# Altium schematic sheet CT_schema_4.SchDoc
size 529 x 503 mm
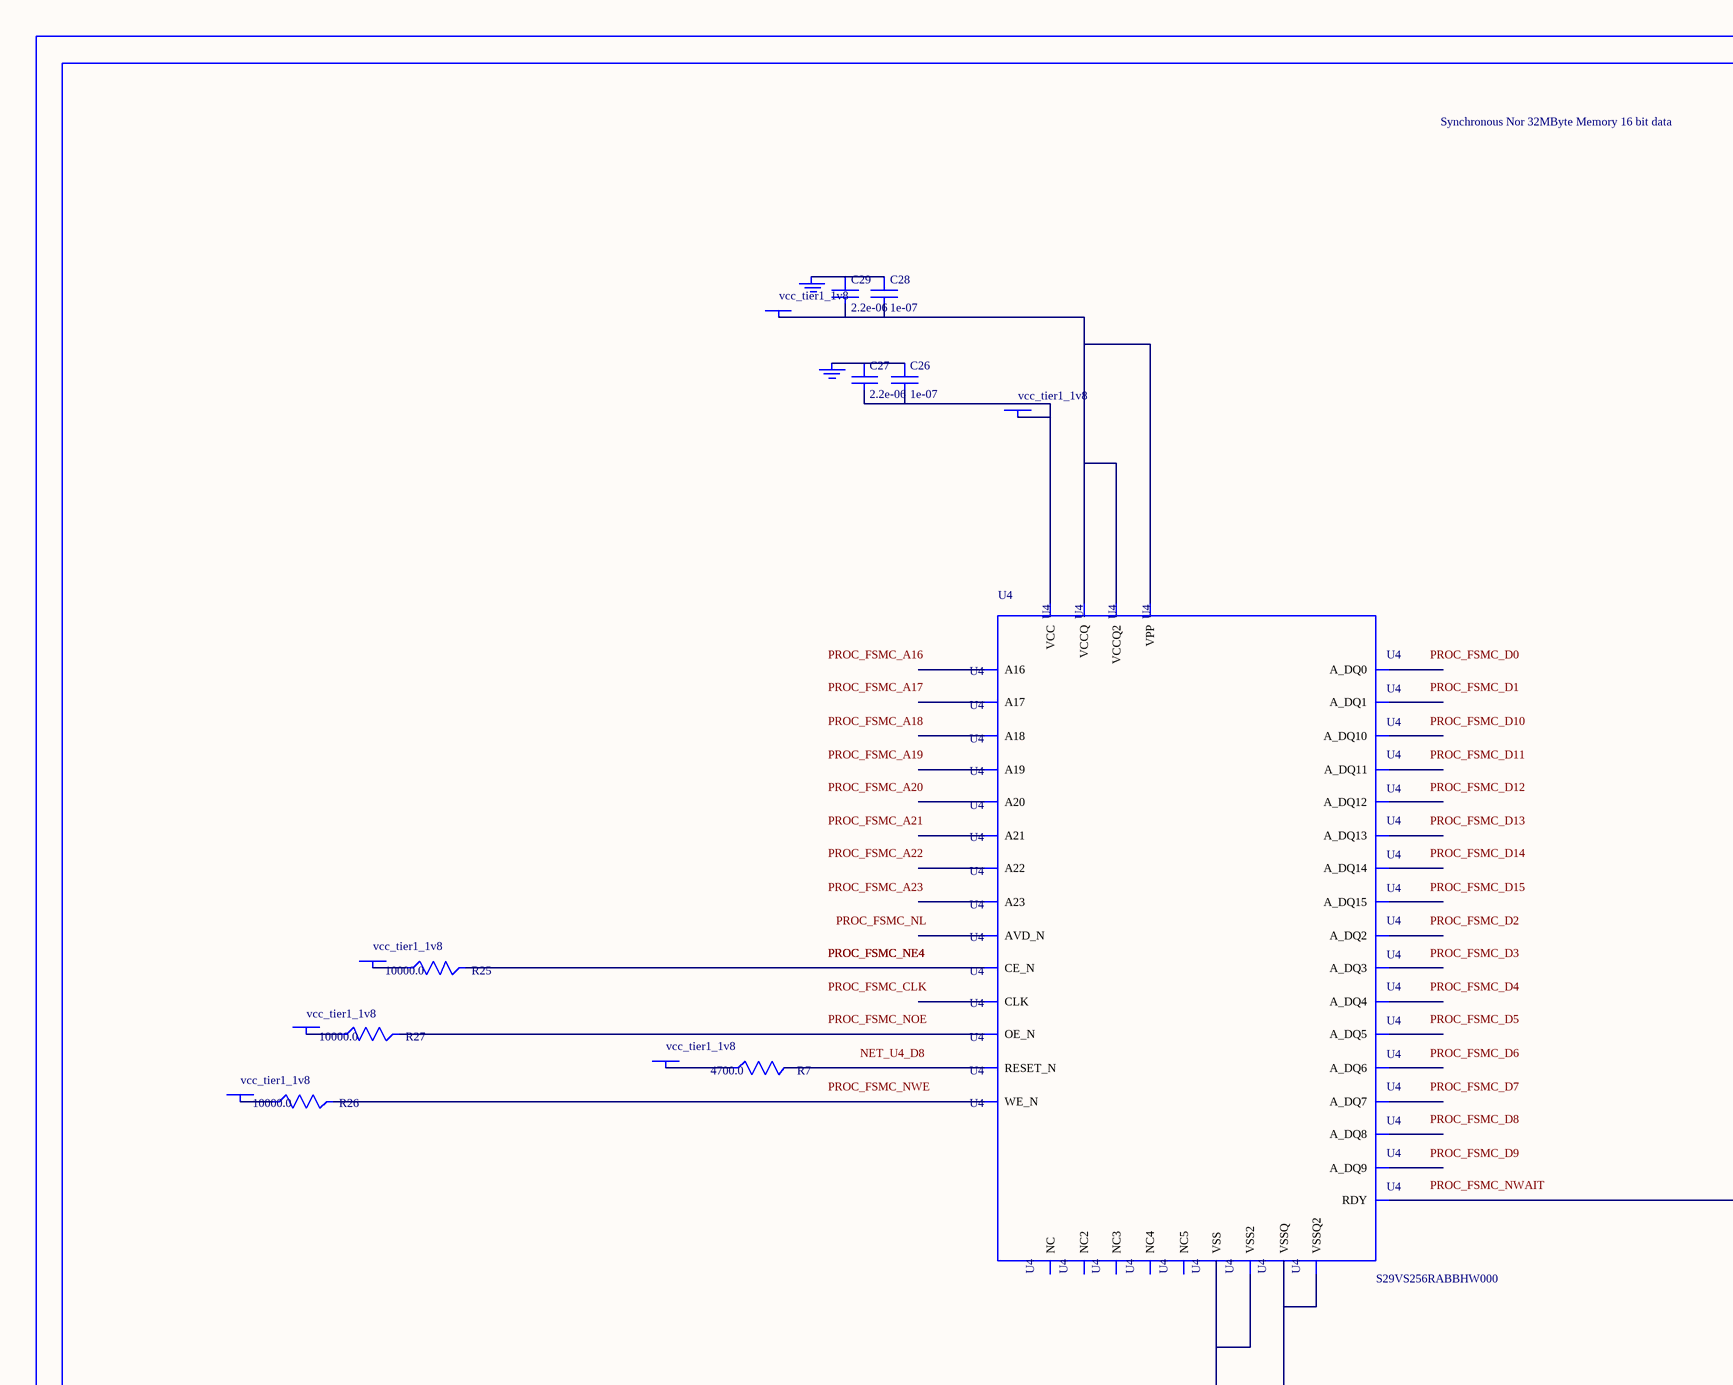
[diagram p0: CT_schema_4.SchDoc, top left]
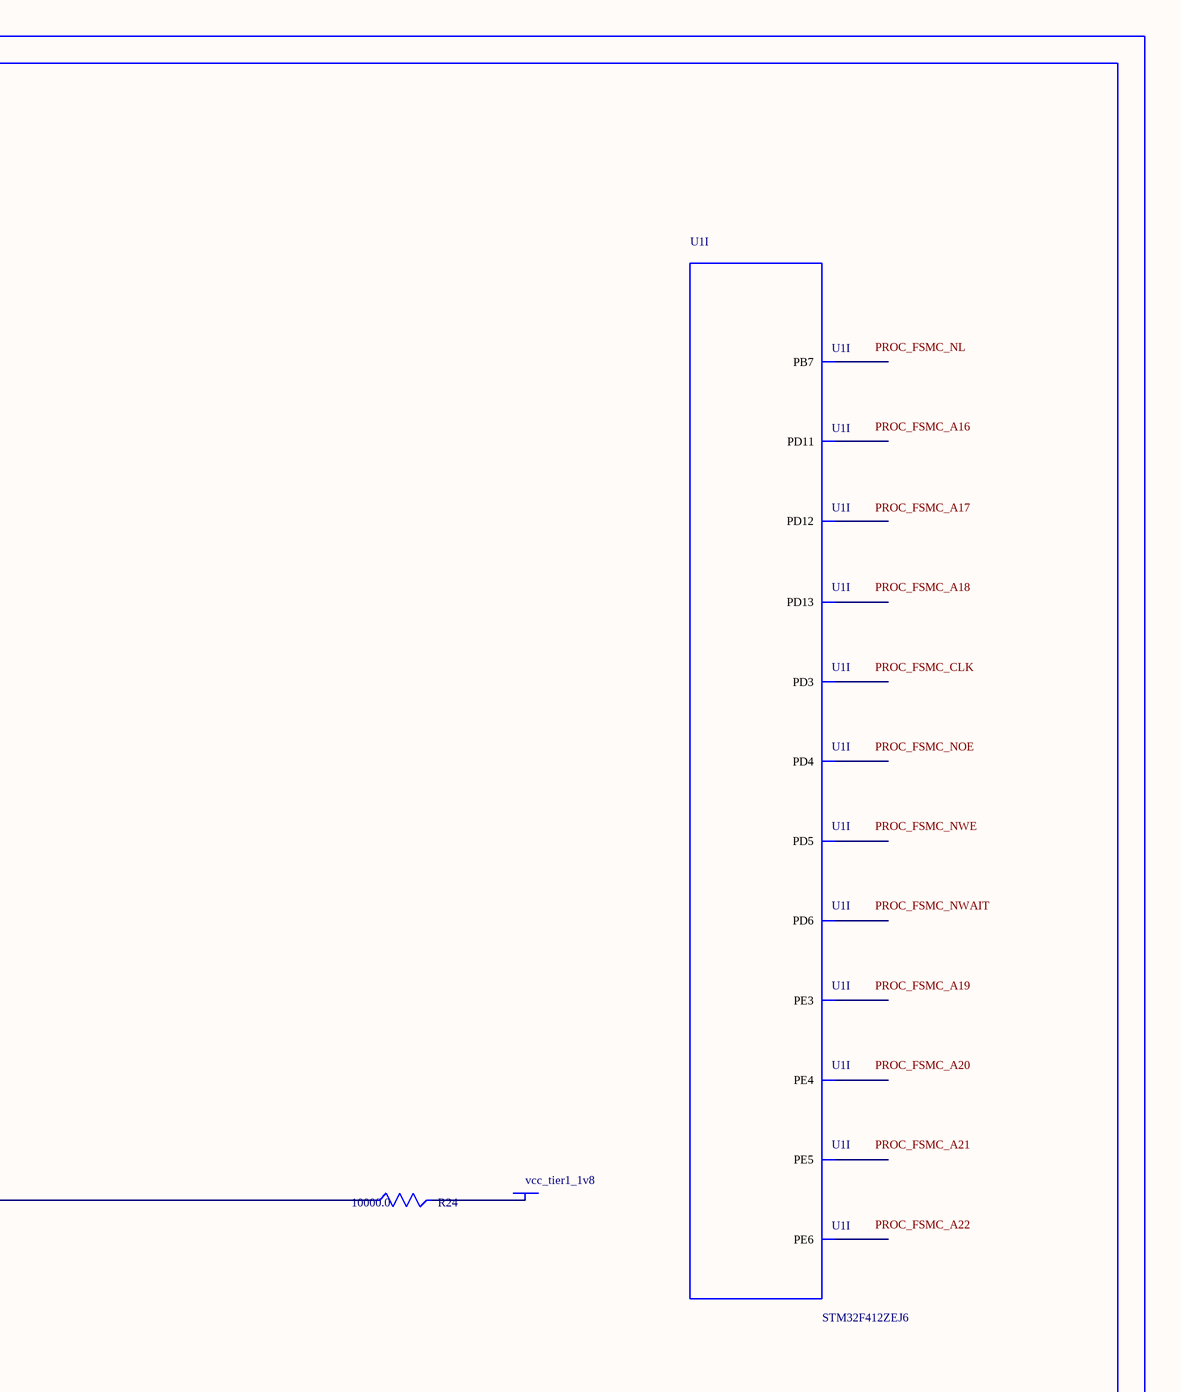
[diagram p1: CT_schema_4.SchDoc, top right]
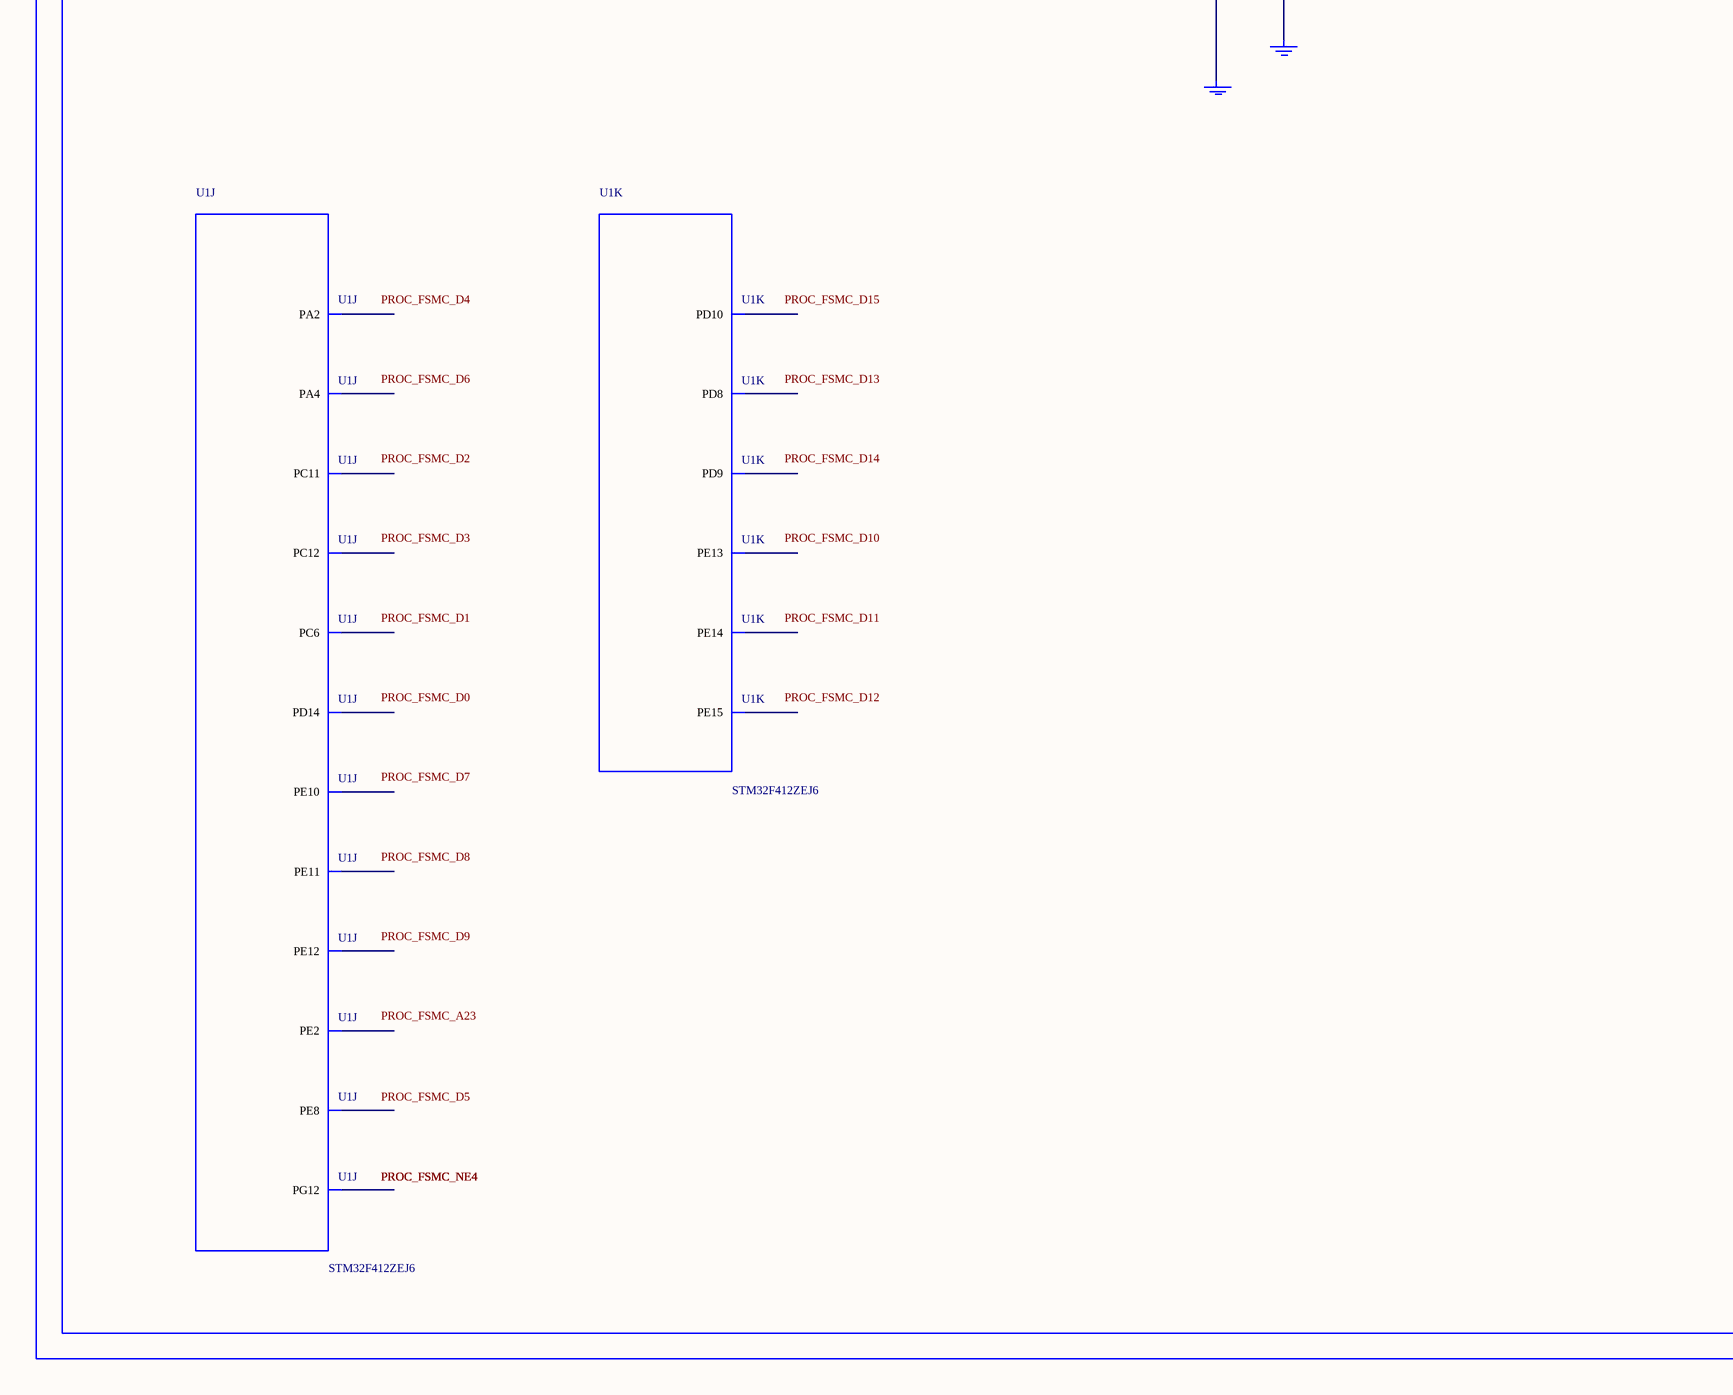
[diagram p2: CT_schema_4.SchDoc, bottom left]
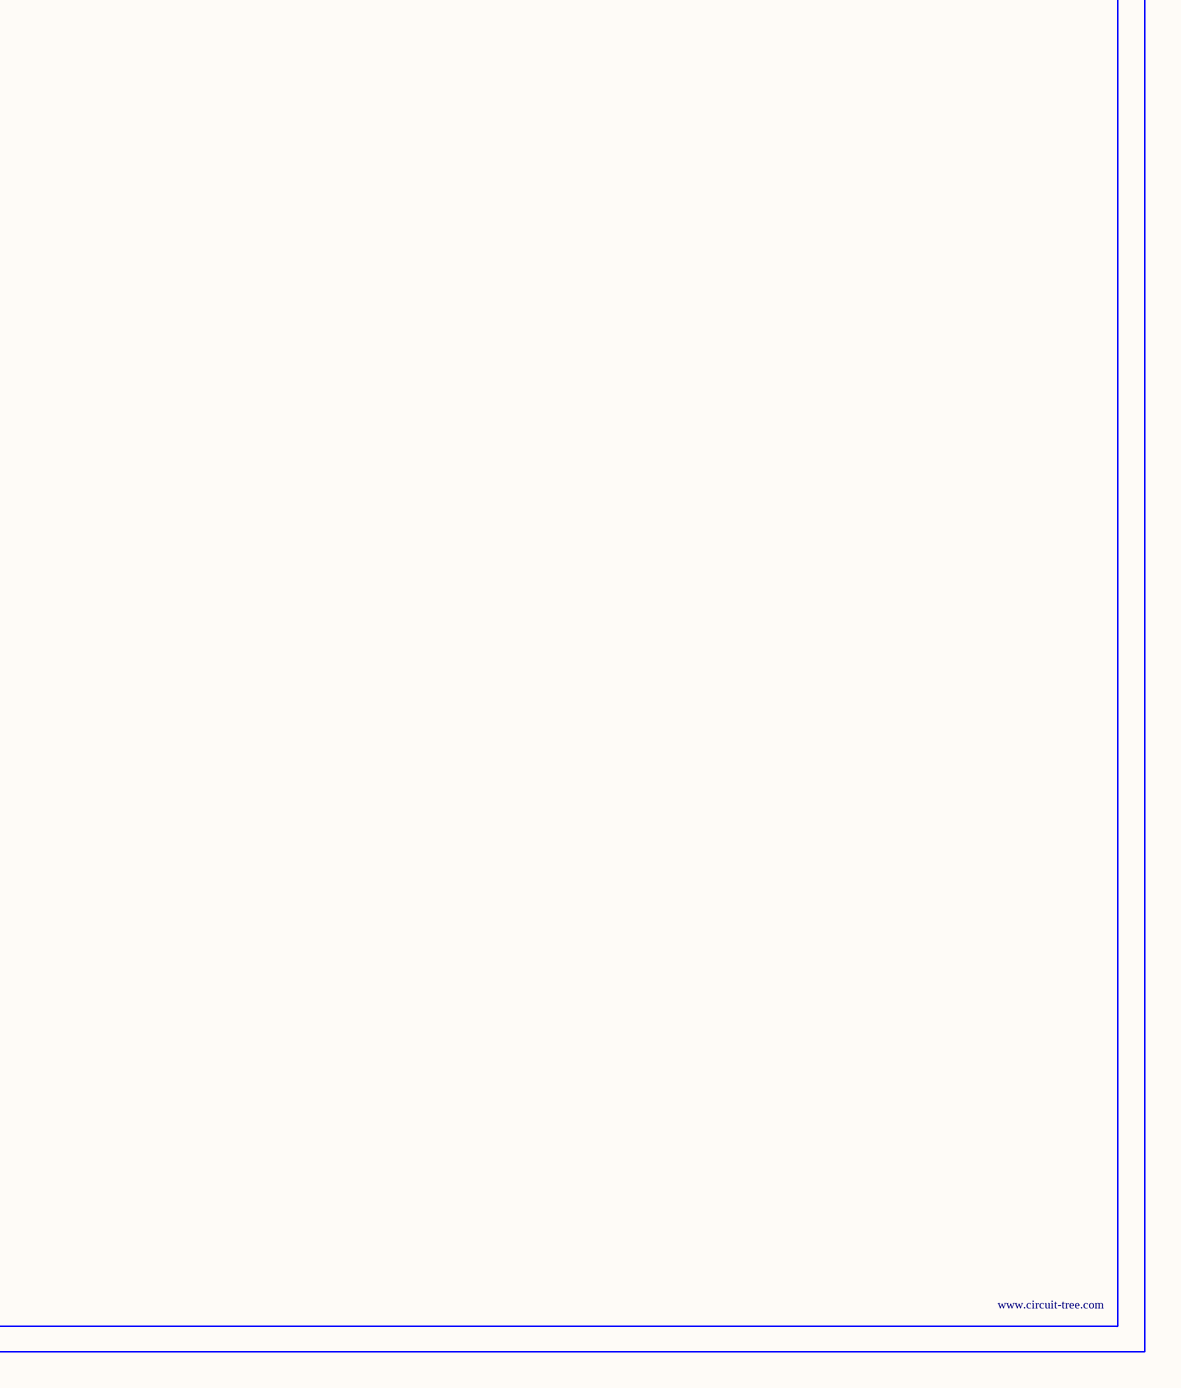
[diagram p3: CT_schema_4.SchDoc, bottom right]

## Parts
BORDER3  (no value)
C26  1e-07  [C0402]
C27  2.2e-06  [C0603]
C28  1e-07  [C0402]
C29  2.2e-06  [C0603]
GND_INSTANCE_3_0  (no value)
GND_INSTANCE_3_1  (no value)
GND_INSTANCE_3_2  (no value)
GND_INSTANCE_3_3  (no value)
POWER_INSTANCE_3_0  vcc_tier1_1v8
POWER_INSTANCE_3_1  vcc_tier1_1v8
POWER_INSTANCE_3_2  vcc_tier1_1v8
POWER_INSTANCE_3_3  vcc_tier1_1v8
POWER_INSTANCE_3_4  vcc_tier1_1v8
POWER_INSTANCE_3_5  vcc_tier1_1v8
POWER_INSTANCE_3_6  vcc_tier1_1v8
R7  4700.0  [R0603]
R24  10000.0  [R0603]
R25  10000.0  [R0603]
R26  10000.0  [R0603]
R27  10000.0  [R0603]
U1  STM32F412ZEJ6  [UFBGA144]  (parts I,J,K of 11)
U4  S29VS256RABBHW000  [S29VS256RABBHW000]

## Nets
NetC26_1: C26.1 C27.1 GND_INSTANCE_3_0.0(GND)
NetC26_2: C26.2 C27.2 POWER_INSTANCE_3_0.0(PWR) U4.C7(VCC)
NetC28_1: C28.1 C29.1 GND_INSTANCE_3_1.0(GND)
NetC28_2: C28.2 C29.2 POWER_INSTANCE_3_1.0(PWR) U4.C9(VPP) U4.D3(VCCQ) U4.F10(VCCQ2)
NetGND_INSTANCE_3_2_0: GND_INSTANCE_3_2.0(GND) U4.C5(VSS) U4.D12(VSS2)
NetGND_INSTANCE_3_3_0: GND_INSTANCE_3_3.0(GND) U4.E3(VSSQ) U4.F5(VSSQ2)
NetPOWER_INSTANCE_3_2_0: POWER_INSTANCE_3_2.0(PWR) R24.2
NetPOWER_INSTANCE_3_3_0: POWER_INSTANCE_3_3.0(PWR) R25.1
NetPOWER_INSTANCE_3_4_0: POWER_INSTANCE_3_4.0(PWR) R26.1
NetPOWER_INSTANCE_3_5_0: POWER_INSTANCE_3_5.0(PWR) R27.1
NetPOWER_INSTANCE_3_6_0: POWER_INSTANCE_3_6.0(PWR) R7.1
NetR7_2: R7.2 U4.D8(RESET_N)
NetR24_1: R24.1 U4.C3(RDY)
NetR25_2: R25.2 U4.D11(CE_N)
NetR26_2: R26.2 U4.C8(WE_N)
NetR27_2: R27.2 U4.E12(OE_N)

Not connected (* = marked no-connect by the designer): U1 A2(PE3) A3(PE2) A8(PD6) B2(PE4) B3(PE5) B4(PE6) B8(PG12) B9(PD5) B10(PC11) C9(PD4) C10(PC12) D6(PB7) D9(PD3) G12(PC6) H8(PE11) H9(PD11) J3(PA4) J7(PE10) J8(PE12) J9(PD10) K8(PE13) K9(PD9) K10(PD13) K11(PD14) L2(PA2) L7(PE8) L8(PE14) L9(PD8) L10(PD12) M8(PE15); U4 A1(NC) A14(NC2) C4(A21) C6(CLK) C10(A19) C11(A17) C12(A22) D4(A16) D5(A20) D6(AVD_N) D7(A23) D9(NC3) D10(A18) E4(A_DQ8) E5(A_DQ9) E6(A_DQ2) E7(A_DQ3) E8(A_DQ12) E9(A_DQ13) E10(A_DQ6) E11(A_DQ7) F3(A_DQ0) F4(A_DQ1) F6(A_DQ10) F7(A_DQ11) F8(A_DQ4) F9(A_DQ5) F11(A_DQ14) F12(A_DQ15) H1(NC4) H14(NC5)

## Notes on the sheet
- Labels drawn without touching a wire or pin: NET_U4_D8, PROC_FSMC_A16, PROC_FSMC_A17, PROC_FSMC_A18, PROC_FSMC_A19, PROC_FSMC_A20, PROC_FSMC_A21, PROC_FSMC_A22, PROC_FSMC_A23, PROC_FSMC_CLK, PROC_FSMC_D0, PROC_FSMC_D1, PROC_FSMC_D2, PROC_FSMC_D3, PROC_FSMC_D4, PROC_FSMC_D5, PROC_FSMC_D6, PROC_FSMC_D7, PROC_FSMC_D8, PROC_FSMC_D9, PROC_FSMC_D10, PROC_FSMC_D11, PROC_FSMC_D12, PROC_FSMC_D13, PROC_FSMC_D14, PROC_FSMC_D15, PROC_FSMC_NL, PROC_FSMC_NOE, PROC_FSMC_NWAIT, PROC_FSMC_NWE

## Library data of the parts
BORDER3 = BORDER_PAGE3
C26 C28 = C0402C104K3RACTU
C27 C29 = C0603C225K8RACTU
GND_INSTANCE_3_0-GND_INSTANCE_3_3 = GND
POWER_INSTANCE_3_0-POWER_INSTANCE_3_6 = PWR
R7 = RC0603JR-074K7L
R24-R27 = RC0603JR-0710KL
